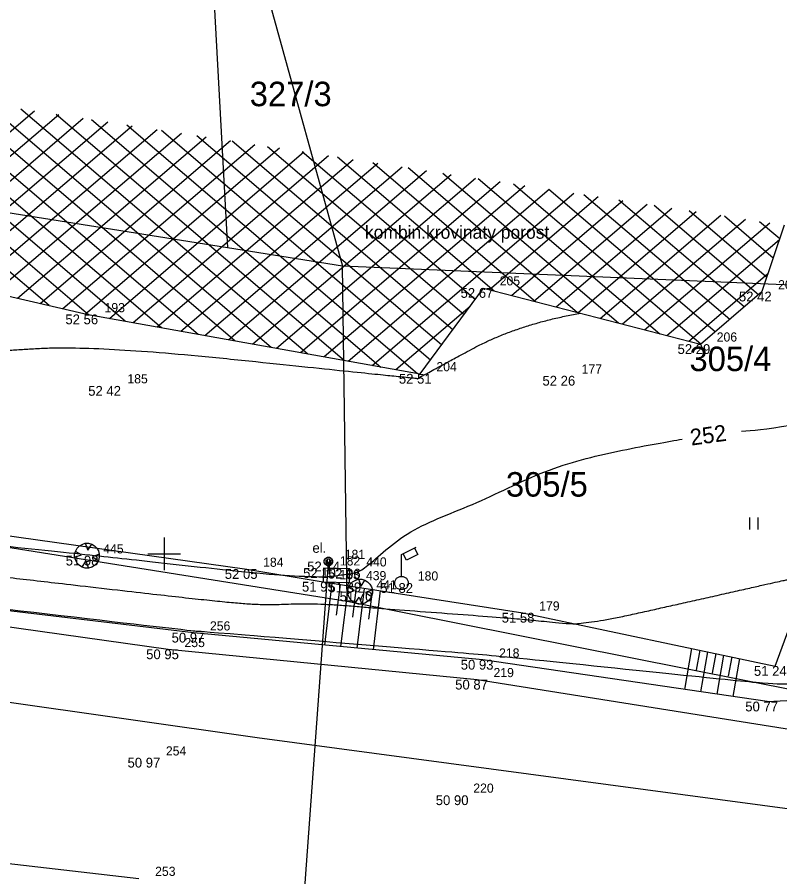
# Model space of a CAD drawing. Extents: x -704057 to -703795, y -1008732 to -1008584.
# Drawn here: x -703954.51 to -703931.14, y -1008659.9 to -1008633.56 of the extents above; entities that cross this region are included whole.
import ezdxf

# ---------------------------------------------------------------- set-up
doc = ezdxf.new("R2010")
doc.units = 0
for name, color, linetype in [('Z_body', 7, 'Continuous'), ('Z_body_cisla', 7, 'Continuous'), ('Z_body_vysky', 7, 'Continuous'), ('Z_hekt_sit', 7, 'Continuous'), ('Z_katastr_cisla_pozemkove', 7, 'Continuous'), ('Z_katastr_hranice', 7, 'Continuous'), ('Z_katastr_hranice_KU', 7, 'Continuous'), ('Z_komunikace_zpevn_pl', 7, 'Continuous'), ('Z_popis', 7, 'Continuous'), ('Z_site_nadz_nerozl', 7, 'Continuous'), ('Z_site_pilire', 7, 'Continuous'), ('Z_site_znaky_elektrika', 7, 'Continuous'), ('Z_site_znaky_VO', 7, 'Continuous'), ('Z_teren_hrany_paty', 7, 'Continuous'), ('Z_vrstevnice_popis', 7, 'Continuous'), ('Z_vrstevnice_vedlejsi', 7, 'Continuous'), ('Z_zelen_jednotliva', 7, 'Continuous'), ('Z_zelen_souvisla', 7, 'Continuous')]:
    doc.layers.add(name, color=color, linetype=linetype)

# ---------------------------------------------------------------- blocks, each defined once
blk = doc.blocks.new('POINT_DISPLAY')
blk.add_line((0, 0), (0, 0))
blk = doc.blocks.new('Z23')
for p, q in [((-0.3, 0.23), (-0.23, 0.3)), ((-0.23, 0.3), (-0.13, 0.35)), ((-0.13, 0.35), (-0.05, 0.38)), ((-0.05, 0.38), (0.05, 0.38)), ((-0.05, 0.38), (0.03, 0.17)), ((0.03, 0.17), (0.15, 0.35)), ((0.05, 0.38), (0.15, 0.35)), ((0.15, 0.35), (0.23, 0.3)), ((0.23, 0.3), (0.3, 0.23)), ((-0.38, 0.05), (-0.35, 0.13)), ((-0.38, -0.05), (-0.38, 0.05)), ((-0.38, -0.05), (-0.17, 0.03)), ((-0.35, 0.13), (-0.3, 0.23)), ((-0.17, 0.03), (-0.35, 0.13)), ((0.38, 0.05), (0.17, -0.03)), ((0.3, 0.23), (0.35, 0.15)), ((0.35, 0.15), (0.38, 0.05)), ((0.38, 0.05), (0.38, -0.05)), ((-0.35, -0.13), (-0.38, -0.05)), ((-0.3, -0.23), (-0.35, -0.13)), ((-0.23, -0.3), (-0.3, -0.23)), ((-0.15, -0.35), (-0.03, -0.17)), ((-0.03, -0.17), (0.05, -0.38)), ((0.17, -0.03), (0.35, -0.15)), ((0.3, -0.23), (0.23, -0.3)), ((0.35, -0.15), (0.3, -0.23)), ((0.38, -0.05), (0.35, -0.15)), ((-0.15, -0.35), (-0.23, -0.3)), ((-0.05, -0.38), (-0.15, -0.35)), ((0.05, -0.38), (-0.05, -0.38)), ((0.15, -0.35), (0.05, -0.38)), ((0.23, -0.3), (0.15, -0.35))]:
    blk.add_line(p, q)
blk = doc.blocks.new('Z13')
for p, q in [((0, 0.88), (0.45, 1.1)), ((0.4, 1.07), (0.5, 0.88)), ((0, 0.2), (0, 0.88)), ((0.15, 0.7), (0.05, 0.9)), ((0.5, 0.88), (0.15, 0.7)), ((-0.2, 0.05), (-0.15, 0.15)), ((-0.2, -0.05), (-0.2, 0.05)), ((-0.15, 0.15), (-0.05, 0.2)), ((-0.05, 0.2), (0.05, 0.2)), ((0.05, 0.2), (0.15, 0.15)), ((0.15, 0.15), (0.2, 0.05)), ((0.2, 0.05), (0.2, -0.05)), ((-0.15, -0.15), (-0.2, -0.05)), ((-0.05, -0.2), (-0.15, -0.15)), ((0.05, -0.2), (-0.05, -0.2)), ((0.15, -0.15), (0.05, -0.2)), ((0.2, -0.05), (0.15, -0.15))]:
    blk.add_line(p, q)
blk = doc.blocks.new('Z601')
for p, q in [((-0.13, 0.03), (-0.1, 0.08)), ((-0.13, -0.03), (-0.13, 0.03)), ((-0.1, 0.08), (-0.08, 0.1)), ((-0.08, 0.1), (-0.03, 0.13)), ((-0.08, 0.05), (-0.08, -0.05)), ((-0.03, 0.13), (0.03, 0.13)), ((-0.03, -0.08), (-0.03, 0.08)), ((-0.03, 0.08), (0.03, 0.08)), ((0.03, 0.13), (0.08, 0.1)), ((0.03, 0.08), (0.03, -0.08)), ((0.08, 0.1), (0.1, 0.08)), ((0.08, -0.05), (0.08, 0.05)), ((0.1, 0.08), (0.13, 0.03)), ((0.13, 0.03), (0.13, -0.03)), ((-0.1, -0.08), (-0.13, -0.03)), ((-0.08, -0.1), (-0.1, -0.08)), ((-0.08, -0.05), (-0.03, -0.08)), ((-0.03, -0.13), (-0.08, -0.1)), ((0.03, -0.13), (-0.03, -0.13)), ((0.03, -0.08), (0.08, -0.05)), ((0.08, -0.1), (0.03, -0.13)), ((0.1, -0.08), (0.08, -0.1)), ((0.13, -0.03), (0.1, -0.08))]:
    blk.add_line(p, q)
blk = doc.blocks.new('Z306')
for p, q in [((-0.13, 0.17), (-0.13, -0.2)), ((0.13, 0.17), (0.13, -0.2))]:
    blk.add_line(p, q)

msp = doc.modelspace()

# ---------------------------------------------------------------- linework, layer by layer
at = {"layer": 'Z_hekt_sit'}
for p, q in [((-703950, -1008649.5), (-703950, -1008650.5)), ((-703950.5, -1008650), (-703949.5, -1008650))]:
    msp.add_line(p, q, dxfattribs=at)
at = {"layer": 'Z_katastr_hranice'}
for p, q in [((-703948.89, -1008625.45), (-703948.06, -1008640.63)), ((-703948.89, -1008625.45), (-703944.54, -1008641.19)), ((-703948.06, -1008640.63), (-703989.44, -1008634.06)), ((-703944.54, -1008641.19), (-703948.06, -1008640.63)), ((-703944.4, -1008651.45), (-703944.54, -1008641.19)), ((-703928.97, -1008641.85), (-703944.54, -1008641.19)), ((-703993.4, -1008643.68), (-703944.4, -1008651.45)), ((-703944.4, -1008651.45), (-703929.24, -1008654.47))]:
    msp.add_line(p, q, dxfattribs=at)
at = {"layer": 'Z_katastr_hranice_KU'}
for p, q in [((-703970.06, -1008652.37), (-703947.15, -1008655.63)), ((-703947.15, -1008655.63), (-703906.73, -1008661.04))]:
    msp.add_line(p, q, dxfattribs=at)
at = {"layer": 'Z_komunikace_zpevn_pl'}
for p, q in [((-703949.88, -1008652.93), (-703958.66, -1008651.71)), ((-703940.41, -1008653.86), (-703949.88, -1008652.93)), ((-703929.26, -1008655.64), (-703940.41, -1008653.86)), ((-703960.94, -1008658.77), (-703950.78, -1008659.95))]:
    msp.add_line(p, q, dxfattribs=at)
at = {"layer": 'Z_site_nadz_nerozl'}
msp.add_line((-703944.98, -1008650.29), (-703946.63, -1008673.02), dxfattribs=at)
at = {"layer": 'Z_site_pilire'}
for p, q in [((-703945.12, -1008650.44), (-703945.13, -1008650.86)), ((-703944.31, -1008650.46), (-703945.12, -1008650.44)), ((-703944.32, -1008650.88), (-703944.31, -1008650.46)), ((-703945.13, -1008650.86), (-703944.32, -1008650.88))]:
    msp.add_line(p, q, dxfattribs=at)
at = {"layer": 'Z_teren_hrany_paty'}
for p, q in [((-703956.38, -1008649.22), (-703947.47, -1008650.47)), ((-703947.47, -1008650.47), (-703945.13, -1008650.86)), ((-703945.13, -1008650.86), (-703939.01, -1008651.81)), ((-703944.86, -1008650.9), (-703945.09, -1008652.8)), ((-703944.61, -1008650.94), (-703944.73, -1008651.88)), ((-703944.36, -1008650.98), (-703944.6, -1008652.84)), ((-703944.12, -1008651.02), (-703944.23, -1008651.94)), ((-703943.87, -1008651.06), (-703944.1, -1008652.89)), ((-703943.62, -1008651.09), (-703943.74, -1008652)), ((-703943.38, -1008651.13), (-703943.6, -1008652.94)), ((-703949.1, -1008652.42), (-703958.09, -1008651.36)), ((-703931.28, -1008653.44), (-703930.5, -1008651.31)), ((-703939.01, -1008651.81), (-703931.28, -1008653.44)), ((-703940.24, -1008653.25), (-703949.1, -1008652.42)), ((-703933.84, -1008652.9), (-703934.06, -1008654.16)), ((-703933.59, -1008652.95), (-703933.7, -1008653.57)), ((-703933.35, -1008653), (-703933.57, -1008654.23)), ((-703933.1, -1008653.06), (-703933.21, -1008653.66)), ((-703931.52, -1008654.53), (-703940.24, -1008653.25)), ((-703932.86, -1008653.11), (-703933.07, -1008654.3)), ((-703932.61, -1008653.16), (-703932.72, -1008653.75)), ((-703932.37, -1008653.21), (-703932.58, -1008654.37)), ((-703931.52, -1008654.53), (-703930.14, -1008654.45))]:
    msp.add_line(p, q, dxfattribs=at)
at = {"layer": 'Z_vrstevnice_popis'}
for points in [[(-703932.312, -1008646.249), (-703931.974, -1008646.22), (-703931.198, -1008646.162), (-703927.689, -1008645.442), (-703927.074, -1008644.896), (-703916.856, -1008644.687)], [(-703971.691, -1008647.995), (-703970.514, -1008648.089), (-703967.379, -1008648.313), (-703964.571, -1008648.435), (-703963.695, -1008648.534), (-703960.428, -1008649.057), (-703958.881, -1008649.241), (-703956.672, -1008649.585), (-703952.719, -1008649.987), (-703950.97, -1008650.177), (-703947.545, -1008650.56), (-703946.3, -1008650.665), (-703945.127, -1008650.72), (-703944.757, -1008650.678), (-703944.314, -1008650.608), (-703943.915, -1008650.57), (-703942.581, -1008649.228), (-703940.433, -1008648.504), (-703938.207, -1008647.326), (-703935.929, -1008646.808), (-703934.536, -1008646.556), (-703934.13, -1008646.489)], [(-703958.782, -1008656.452), (-703958.711, -1008656.345), (-703958.126, -1008655.591), (-703956.246, -1008655.482), (-703959.788, -1008654.246), (-703961.93, -1008651.293), (-703961.78, -1008651.126), (-703959.248, -1008651.187), (-703958.2, -1008651.305), (-703958.136, -1008651.315), (-703958.106, -1008651.318), (-703958.062, -1008651.325), (-703957.976, -1008651.334), (-703949.197, -1008652.35), (-703949.055, -1008652.366), (-703948.978, -1008652.372), (-703948.89, -1008652.368), (-703940.582, -1008653.06), (-703940.108, -1008653.095), (-703933.647, -1008653.758), (-703931.403, -1008653.997), (-703930.745, -1008653.985), (-703930.26, -1008654), (-703929.245, -1008652.825), (-703928.701, -1008652.453), (-703928.643, -1008652.6), (-703928.429, -1008652.279), (-703926.218, -1008652.574), (-703924.884, -1008652.504), (-703924.716, -1008652.484), (-703922.063, -1008653.995), (-703921.911, -1008654.006), (-703921.781, -1008654.024), (-703921.558, -1008654.048), (-703920.173, -1008654.162), (-703919.91, -1008654.188), (-703916.508, -1008654.023), (-703914.694, -1008654.331), (-703914.465, -1008654.432), (-703913.706, -1008654.968), (-703913.145, -1008655.151), (-703910.497, -1008655.228), (-703905.972, -1008655.203), (-703903.752, -1008655.504), (-703902.532, -1008655.695)]]:
    msp.add_open_spline(points, degree=3, dxfattribs=at)
at = {"layer": 'Z_vrstevnice_vedlejsi'}
for points in [[(-704009.362, -1008633.586), (-704007.915, -1008634.739), (-704007.143, -1008635.358), (-704002.876, -1008638.286), (-704002.679, -1008638.43), (-704002.255, -1008638.718), (-704001.165, -1008638.717), (-703995.889, -1008642.289), (-703994.89, -1008642.862), (-703994.417, -1008642.752), (-703993.832, -1008642.719), (-703993.258, -1008640.696), (-703993.341, -1008639.701), (-703993.272, -1008639.432), (-703993.04, -1008638.835), (-703992.99, -1008638.745), (-703990.403, -1008638.423), (-703989.481, -1008638.539), (-703989.058, -1008638.588), (-703989.018, -1008638.516), (-703988.578, -1008638.54), (-703988.475, -1008638.554), (-703988.362, -1008638.685), (-703988.319, -1008638.754), (-703988.294, -1008638.815), (-703986.637, -1008641.391), (-703986.518, -1008641.581), (-703985.267, -1008643.657), (-703984.422, -1008644.955), (-703982.223, -1008646.72), (-703982.083, -1008646.9), (-703980.47, -1008647.779), (-703979.335, -1008647.914), (-703971.793, -1008648.878), (-703969.312, -1008649.063), (-703968.076, -1008649.117), (-703960.948, -1008649.919), (-703959.282, -1008650.186), (-703958.493, -1008650.28), (-703957.367, -1008650.455), (-703955.116, -1008650.684), (-703950.816, -1008651.182), (-703948.3, -1008651.463), (-703946.953, -1008651.576), (-703945.397, -1008651.505), (-703943.023, -1008651.703), (-703939.161, -1008651.987), (-703938.27, -1008652.079), (-703937.191, -1008652.194), (-703934.147, -1008651.524), (-703931.028, -1008650.815), (-703930.717, -1008650.764), (-703928.94, -1008650.83), (-703928.501, -1008650.751), (-703928.424, -1008650.713), (-703928.413, -1008650.708), (-703928.266, -1008650.724), (-703926.027, -1008648.737), (-703920.5, -1008648.624), (-703915.824, -1008649.925), (-703908.88, -1008649.843), (-703904.651, -1008650.155), (-703897.103, -1008651.333), (-703893.743, -1008651.997), (-703889.99, -1008652.252), (-703881.693, -1008653.228), (-703874.656, -1008652.961), (-703868.448, -1008652.365), (-703859.857, -1008652.906), (-703856.36, -1008653.001), (-703843.765, -1008653.766), (-703842.17, -1008653.801), (-703841.143, -1008653.824), (-703831.904, -1008654.28)], [(-703988.164, -1008635.52), (-703987.276, -1008636.976), (-703986.008, -1008640.062), (-703985.47, -1008640.897), (-703984.895, -1008641.813), (-703984.686, -1008642.159), (-703982.65, -1008645.287), (-703982.397, -1008645.49), (-703982.043, -1008645.946), (-703981.661, -1008646.154), (-703977.458, -1008646.656), (-703976.772, -1008646.743), (-703972.443, -1008647.066), (-703969.747, -1008647.327), (-703967.111, -1008646.193), (-703965.337, -1008645.561), (-703960.636, -1008644.491), (-703957.873, -1008644.043), (-703955.63, -1008643.808), (-703952.03, -1008643.609), (-703943.212, -1008644.531), (-703942.275, -1008644.62), (-703942.236, -1008644.645), (-703942.208, -1008644.623), (-703942.168, -1008644.583), (-703942.126, -1008644.569), (-703941.982, -1008644.492), (-703939.179, -1008642.975), (-703937.245, -1008642.629)], [(-703944.218, -1008669.537), (-703942.215, -1008669.847), (-703941.835, -1008669.79), (-703940.983, -1008669.911), (-703940.538, -1008669.059), (-703940.441, -1008669.011), (-703939.659, -1008668.87), (-703938.392, -1008666.573), (-703937.218, -1008665.198), (-703936.994, -1008664.158), (-703936.811, -1008663.182), (-703935.504, -1008662.788), (-703930.851, -1008662.989), (-703930.683, -1008662.945), (-703930.514, -1008662.948), (-703928.53, -1008663.14), (-703926.451, -1008662.869), (-703924.285, -1008662.962), (-703918.453, -1008660.188), (-703917.529, -1008662.583), (-703908.804, -1008661.73), (-703914.417, -1008658.58), (-703914.255, -1008657.775), (-703916.458, -1008657.408), (-703916.075, -1008656.975), (-703916.505, -1008656.883), (-703916.435, -1008655.703), (-703915.746, -1008656.007), (-703915.438, -1008656.225), (-703913.541, -1008656.36), (-703913.202, -1008656.502), (-703907.93, -1008657.256), (-703905.824, -1008657.417), (-703900.033, -1008658.024), (-703894.345, -1008658.848), (-703890.179, -1008659.57), (-703887.702, -1008659.871), (-703882.266, -1008660.175), (-703878.347, -1008660.959), (-703873.149, -1008661.531), (-703869.803, -1008661.293), (-703867.148, -1008661.514), (-703856.66, -1008662.48), (-703848.555, -1008661.935), (-703843.582, -1008661.747), (-703840.018, -1008661.713), (-703835.656, -1008661.182), (-703832.168, -1008661.259), (-703831.497, -1008661.293), (-703819.488, -1008662.346), (-703817.521, -1008662.543), (-703807.841, -1008663.114), (-703805.78, -1008663.132)]]:
    msp.add_open_spline(points, degree=2, dxfattribs=at)
at = {"layer": 'Z_zelen_souvisla'}
for p, q in [((-703961.93, -1008635.22), (-703953.53, -1008642.39)), ((-703960.85, -1008635.38), (-703952.32, -1008642.67)), ((-703959.78, -1008635.55), (-703951.2, -1008642.87)), ((-703958.7, -1008635.71), (-703950.08, -1008643.07)), ((-703957.62, -1008635.87), (-703948.96, -1008643.27)), ((-703956.54, -1008636.04), (-703947.84, -1008643.47)), ((-703955.46, -1008636.2), (-703946.72, -1008643.67)), ((-703959.37, -1008641.04), (-703953.98, -1008636.43)), ((-703954.39, -1008636.37), (-703945.6, -1008643.88)), ((-703958.68, -1008641.2), (-703953.23, -1008636.54)), ((-703957.98, -1008641.36), (-703952.48, -1008636.66)), ((-703953.31, -1008636.53), (-703944.48, -1008644.08)), ((-703952.23, -1008636.7), (-703943.36, -1008644.28)), ((-703957.29, -1008641.52), (-703951.73, -1008636.77)), ((-703956.59, -1008641.68), (-703950.98, -1008636.89)), ((-703955.89, -1008641.84), (-703950.22, -1008637)), ((-703951.15, -1008636.86), (-703942.24, -1008644.48)), ((-703955.2, -1008642), (-703949.47, -1008637.12)), ((-703954.5, -1008642.17), (-703948.72, -1008637.23)), ((-703950.08, -1008637.02), (-703941.84, -1008644.06)), ((-703949, -1008637.19), (-703941.5, -1008643.59)), ((-703953.8, -1008642.33), (-703947.97, -1008637.34)), ((-703953.11, -1008642.49), (-703947.22, -1008637.46)), ((-703947.92, -1008637.35), (-703941.16, -1008643.13)), ((-703946.84, -1008637.52), (-703940.81, -1008642.67)), ((-703952.41, -1008642.65), (-703946.47, -1008637.57)), ((-703951.68, -1008642.79), (-703945.72, -1008637.69)), ((-703945.77, -1008637.68), (-703940.47, -1008642.2)), ((-703950.95, -1008642.92), (-703944.97, -1008637.8)), ((-703950.22, -1008643.05), (-703944.21, -1008637.92)), ((-703949.49, -1008643.18), (-703943.46, -1008638.03)), ((-703944.69, -1008637.84), (-703939.89, -1008641.95)), ((-703943.61, -1008638.01), (-703938.62, -1008642.27)), ((-703948.76, -1008643.31), (-703942.71, -1008638.15)), ((-703948.02, -1008643.44), (-703941.96, -1008638.26)), ((-703942.53, -1008638.17), (-703937.35, -1008642.6)), ((-703947.29, -1008643.57), (-703941.21, -1008638.38)), ((-703946.56, -1008643.7), (-703940.46, -1008638.49)), ((-703941.46, -1008638.34), (-703936.08, -1008642.93)), ((-703940.38, -1008638.5), (-703934.81, -1008643.26)), ((-703945.83, -1008643.83), (-703939.71, -1008638.6)), ((-703945.1, -1008643.96), (-703938.95, -1008638.72)), ((-703944.36, -1008644.1), (-703938.2, -1008638.83)), ((-703939.3, -1008638.67), (-703933.56, -1008643.57)), ((-703938.22, -1008638.83), (-703933.12, -1008643.19)), ((-703943.63, -1008644.23), (-703937.45, -1008638.95)), ((-703940.03, -1008641.91), (-703936.7, -1008639.06)), ((-703937.14, -1008638.99), (-703932.67, -1008642.81)), ((-703939.35, -1008642.08), (-703935.95, -1008639.18)), ((-703938.67, -1008642.26), (-703935.2, -1008639.29)), ((-703936.07, -1008639.16), (-703932.23, -1008642.43)), ((-703934.99, -1008639.32), (-703931.79, -1008642.06)), ((-703937.99, -1008642.44), (-703934.45, -1008639.41)), ((-703937.32, -1008642.61), (-703933.7, -1008639.52)), ((-703936.64, -1008642.79), (-703932.94, -1008639.63)), ((-703933.91, -1008639.49), (-703931.54, -1008641.52)), ((-703935.96, -1008642.96), (-703932.19, -1008639.75)), ((-703935.28, -1008643.14), (-703931.44, -1008639.86)), ((-703932.83, -1008639.65), (-703931.34, -1008640.93)), ((-703931.76, -1008639.82), (-703931.14, -1008640.34)), ((-703931, -1008639.93), (-703931.69, -1008641.97)), ((-703934.6, -1008643.31), (-703931.15, -1008640.37)), ((-703960.39, -1008640.8), (-703952.33, -1008642.67)), ((-703933.92, -1008643.49), (-703931.51, -1008641.43)), ((-703942.16, -1008644.49), (-703940.22, -1008641.86)), ((-703940.22, -1008641.86), (-703933.57, -1008643.58)), ((-703933.57, -1008643.58), (-703931.69, -1008641.97)), ((-703942.9, -1008644.36), (-703940.63, -1008642.42)), ((-703952.33, -1008642.67), (-703942.16, -1008644.49))]:
    msp.add_line(p, q, dxfattribs=at)

# ---------------------------------------------------------------- block references
at = {"layer": 'Z_body'}
for p in [(-703940.22, -1008641.86), (-703931.69, -1008641.97), (-703952.33, -1008642.67), (-703933.57, -1008643.58), (-703942.16, -1008644.49), (-703937.71, -1008644.55), (-703951.63, -1008644.86), (-703952.37, -1008650.06), (-703944.97, -1008650.24), (-703947.47, -1008650.47), (-703945.12, -1008650.44), (-703944.31, -1008650.46), (-703945.13, -1008650.86), (-703944.32, -1008650.88), (-703942.73, -1008650.9), (-703944, -1008651.16), (-703939.01, -1008651.81), (-703949.1, -1008652.42), (-703949.88, -1008652.93), (-703940.24, -1008653.25), (-703931.28, -1008653.44), (-703940.41, -1008653.86), (-703931.52, -1008654.53), (-703950.45, -1008656.25), (-703941.03, -1008657.4)]:
    msp.add_blockref('POINT_DISPLAY', p, dxfattribs=at)
at = {"layer": 'Z_popis'}
msp.add_blockref('Z306', (-703931.94, -1008649.06), dxfattribs=at)
at = {"layer": 'Z_site_znaky_elektrika'}
msp.add_blockref('Z601', (-703944.97, -1008650.24), dxfattribs=at)
at = {"layer": 'Z_site_znaky_VO'}
msp.add_blockref('Z13', (-703942.73, -1008650.9), dxfattribs=at)
at = {"layer": 'Z_zelen_jednotliva'}
for p in [(-703952.37, -1008650.06), (-703944, -1008651.16)]:
    msp.add_blockref('Z23', p, dxfattribs=at)

# ---------------------------------------------------------------- texts
at = {"layer": 'Z_body_cisla'}
for s, p in [('205', (-703939.72, -1008641.78)), ('207', (-703931.19, -1008641.9)), ('193', (-703951.83, -1008642.6)), ('206', (-703933.07, -1008643.5)), ('204', (-703941.66, -1008644.41)), ('177', (-703937.21, -1008644.48)), ('185', (-703951.13, -1008644.78)), ('445', (-703951.87, -1008649.99)), ('181', (-703944.47, -1008650.16)), ('184', (-703946.97, -1008650.4)), ('182', (-703944.62, -1008650.36)), ('440', (-703943.81, -1008650.39)), ('183', (-703944.63, -1008650.78)), ('439', (-703943.82, -1008650.81)), ('180', (-703942.23, -1008650.82)), ('441', (-703943.5, -1008651.09)), ('179', (-703938.51, -1008651.74)), ('256', (-703948.6, -1008652.35)), ('255', (-703949.38, -1008652.86)), ('218', (-703939.74, -1008653.18)), ('219', (-703939.91, -1008653.78)), ('254', (-703949.95, -1008656.18)), ('220', (-703940.53, -1008657.32)), ('253', (-703950.28, -1008659.87))]:
    msp.add_text(s, height=0.28, dxfattribs=at).set_placement(p)
at = {"layer": 'Z_body_vysky'}
for s, p in [('52 67', (-703940.92, -1008642.16)), ('52 42', (-703932.39, -1008642.27)), ('52 56', (-703953.03, -1008642.97)), ('52 29', (-703934.27, -1008643.88)), ('52 51', (-703942.81, -1008644.79)), ('52 26', (-703938.41, -1008644.85)), ('52 42', (-703952.33, -1008645.16)), ('51 98', (-703953.02, -1008650.36)), ('52 10', (-703945.745, -1008650.74)), ('52 14', (-703945.62, -1008650.54)), ('52 05', (-703948.145, -1008650.77)), ('52 06', (-703944.985, -1008650.76)), ('51 95', (-703945.78, -1008651.16)), ('51 89', (-703944.97, -1008651.18)), ('51 82', (-703943.38, -1008651.2)), ('51 70', (-703944.625, -1008651.46)), ('51 58', (-703939.66, -1008652.11)), ('50 97', (-703949.775, -1008652.72)), ('50 95', (-703950.555, -1008653.23)), ('50 93', (-703940.915, -1008653.55)), ('51 24', (-703931.93, -1008653.74)), ('50 87', (-703941.085, -1008654.16)), ('50 77', (-703932.195, -1008654.83)), ('50 97', (-703951.125, -1008656.55)), ('50 90', (-703941.68, -1008657.7))]:
    msp.add_text(s, height=0.3, dxfattribs=at).set_placement(p)
at = {"layer": 'Z_katastr_cisla_pozemkove'}
for s, p in [('327/3', (-703947.38, -1008636.29)), ('305/4', (-703933.905, -1008644.405)), ('305/5', (-703939.53, -1008648.25))]:
    msp.add_text(s, height=0.75, dxfattribs=at).set_placement(p)
at = {"layer": 'Z_popis'}
for s, height, p in [('kombin.krovinaty porost', 0.4, (-703943.85, -1008640.35)), ('el.', 0.3, (-703945.459, -1008649.971))]:
    msp.add_text(s, height=height, dxfattribs=at).set_placement(p)
at = {"layer": 'Z_vrstevnice_popis'}
msp.add_text('252', height=0.5, rotation=7.8579, dxfattribs=at).set_placement((-703933.85, -1008646.688))

doc.saveas('drawing.dxf')
